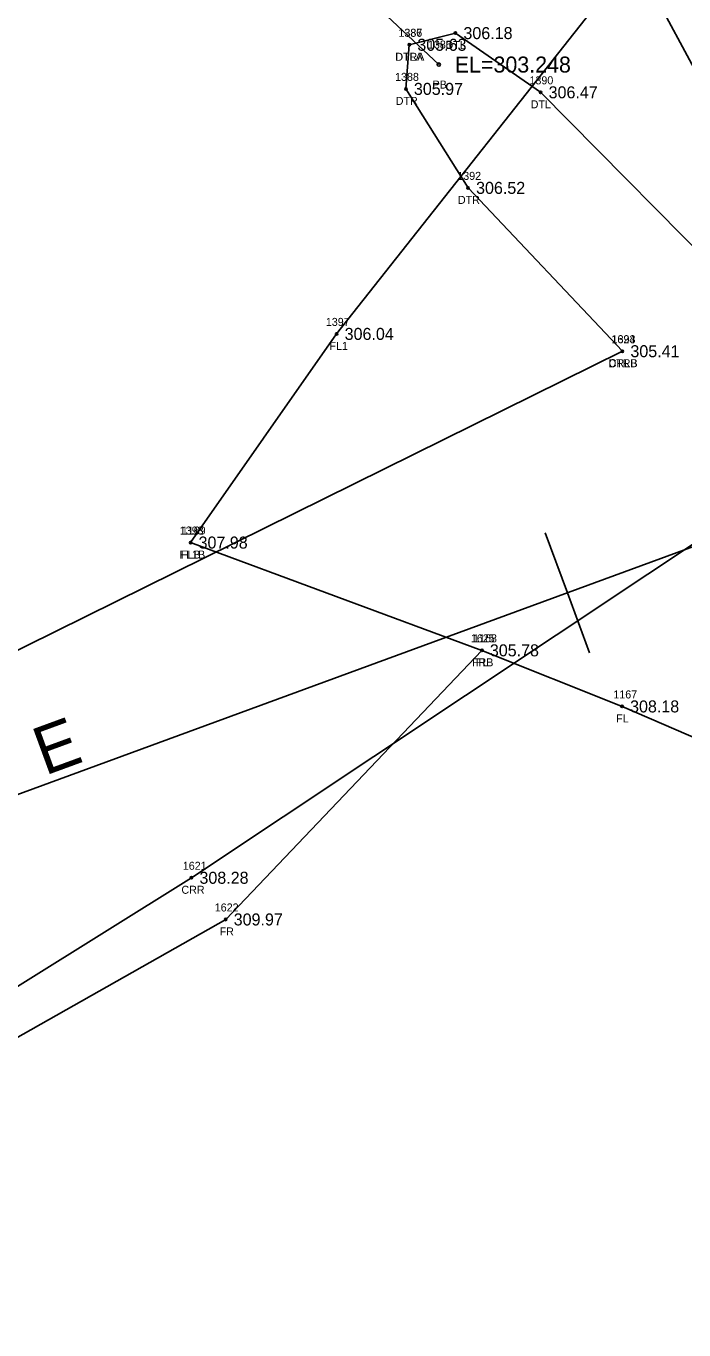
# Model space of a CAD drawing. Extents: x 1865045 to 1867370, y 910391 to 914218.
# Drawn here: x 1866241.8 to 1866324, y 910971.7 to 911134.6 of the extents above; entities that cross this region are included whole.
import ezdxf

# ---------------------------------------------------------------- set-up
doc = ezdxf.new("R2010")
doc.units = 0
for name, color, linetype in [('RD_EX_DR_Pipe', 7, 'Continuous'), ('RD_EX_DR_Pipe_txCode', 7, 'Continuous'), ('RD_EX_Fence_Other', 7, 'Continuous'), ('RD_EX_Fence_Other_txCode', 7, 'Continuous'), ('RD_EX_H2O', 7, 'Continuous'), ('RD_EX_H2O_txCode', 7, 'Continuous'), ('RD_EX_TX_Fence_Other_ELEV', 7, 'Continuous'), ('RD_EX_TX_H2O_ELEV', 7, 'Continuous'), ('RD_HC_Cl', 7, 'Continuous'), ('RD_HC_Data', 7, 'Continuous'), ('RD_HC_Data_Tic', 7, 'Continuous'), ('RD_SMD_Locator', 7, 'Continuous'), ('RD_TX_Pipe_ElevEX', 7, 'Continuous')]:
    doc.layers.add(name, color=color, linetype=linetype)

msp = doc.modelspace()

# ---------------------------------------------------------------- linework, layer by layer
at = {"layer": 'RD_EX_DR_Pipe'}
msp.add_line((1866280.05, 911142.32), (1866293.34, 911129.82), dxfattribs=at)
at = {"layer": 'RD_EX_Fence_Other'}
for points in [[(1866328.11, 911123.98), (1866317.73, 911143.27), (1866292.21, 911196.64), (1866254.72, 911273.66), (1866198.8, 911388.88), (1866160.41, 911467.37), (1866132.32, 911522.75), (1866123.76, 911516.89), (1866120.96, 911520.71)], [(1866317.73, 911143.27), (1866280.58, 911096.16), (1866262.33, 911070.09)], [(1866495.48, 910749.21), (1866508.82, 910756.58), (1866493.03, 910785.29), (1866469.81, 910829.93), (1866443.69, 910882.22), (1866422.34, 910922.89), (1866379.46, 911022.29), (1866316.24, 911049.61), (1866298.72, 911056.62), (1866262.33, 911070.09)], [(1865878.66, 910821.99), (1865958.17, 910874.52), (1866026.09, 910916.1), (1866080.13, 910930.26), (1866132.1, 910957.01), (1866200.24, 910985.36), (1866266.72, 911022.99), (1866298.72, 911056.62)]]:
    msp.add_lwpolyline(points, dxfattribs=at)
at = {"layer": 'RD_EX_H2O'}
for points in [[(1866289.66, 911132.29), (1866295.42, 911133.75), (1866306.06, 911126.35), (1866331.08, 911101.06)], [(1866289.66, 911132.29), (1866289.23, 911126.78), (1866297, 911114.41), (1866316.28, 911094)], [(1865881.51, 910820.06), (1865958.27, 910871.4), (1866021.41, 910928.56), (1866077.02, 910947.47), (1866128.62, 910963.47), (1866198.85, 910988.48), (1866262.44, 911028.2), (1866342.24, 911081.3), (1866369.75, 911075.31), (1866430.98, 911110.24)], [(1865861.04, 910849.84), (1865929.7, 910901.29), (1866000.34, 910964.46), (1866054.46, 911008.9), (1866114.23, 911001.05), (1866184.96, 911030.79), (1866234.29, 911053.46), (1866316.28, 911094)]]:
    msp.add_lwpolyline(points, dxfattribs=at)
at = {"layer": 'RD_HC_Cl'}
msp.add_line((1866069.86, 910975.96), (1866379.46, 911089.5), dxfattribs=at)
at = {"layer": 'RD_HC_Data_Tic'}
for q in [(1866306.65, 911071.31), (1866312.15, 911056.29)]:
    msp.add_line((1866309.4, 911063.8), q, dxfattribs=at)
at = {"layer": 'RD_SMD_Locator'}
for centre, radius in [((1866289.66, 911132.29), 0.15), ((1866289.66, 911132.29), 0.15), ((1866295.42, 911133.75), 0.15), ((1866293.34, 911129.82), 0.2), ((1866289.23, 911126.78), 0.15), ((1866306.06, 911126.35), 0.15), ((1866297, 911114.41), 0.15), ((1866280.58, 911096.16), 0.15), ((1866316.28, 911094), 0.15), ((1866316.28, 911094), 0.15), ((1866262.33, 911070.09), 0.15), ((1866262.33, 911070.09), 0.15), ((1866298.72, 911056.62), 0.15), ((1866298.72, 911056.62), 0.15), ((1866316.24, 911049.61), 0.15), ((1866262.44, 911028.2), 0.15), ((1866266.72, 911022.99), 0.15)]:
    msp.add_circle(centre, radius, dxfattribs=at)

# ---------------------------------------------------------------- texts
at = {"layer": 'RD_EX_DR_Pipe_txCode'}
for s, p in [('1385', (1866291.99, 911131.82)), ('PB', (1866292.56, 911126.82))]:
    msp.add_text(s, height=1, dxfattribs=at).set_placement(p)
at = {"layer": 'RD_EX_Fence_Other_txCode'}
for s, p in [('1397', (1866279.23, 911097.16)), ('FL1', (1866279.68, 911094.16)), ('1398', (1866260.98, 911071.09)), ('1169', (1866261.24, 911071.09)), ('FL1B', (1866260.96, 911068.09)), ('FLB', (1866261.12, 911068.09)), ('1625', (1866297.35, 911057.62)), ('1168', (1866297.63, 911057.62)), ('FRB', (1866297.49, 911054.62)), ('FL', (1866297.98, 911054.62)), ('1167', (1866315.15, 911050.61)), ('FL', (1866315.5, 911047.61)), ('1622', (1866265.35, 911023.99)), ('FR', (1866265.96, 911020.99))]:
    msp.add_text(s, height=1, dxfattribs=at).set_placement(p)
at = {"layer": 'RD_EX_H2O_txCode'}
for s, p in [('1386', (1866288.29, 911133.29)), ('1387', (1866288.31, 911133.29)), ('DTL', (1866294.18, 911131.75)), ('DTRA', (1866287.9, 911130.29)), ('DTLA', (1866287.92, 911130.29)), ('1388', (1866287.88, 911127.78)), ('1390', (1866304.67, 911127.35)), ('DTR', (1866287.96, 911124.78)), ('DTL', (1866304.82, 911124.35)), ('1392', (1866295.65, 911115.41)), ('DTR', (1866295.73, 911112.41)), ('1624', (1866314.91, 911095)), ('1393', (1866314.94, 911095)), ('CRLB', (1866314.58, 911092)), ('DTRB', (1866314.54, 911092)), ('1621', (1866261.36, 911029.2)), ('CRR', (1866261.19, 911026.2))]:
    msp.add_text(s, height=1, dxfattribs=at).set_placement(p)
at = {"layer": 'RD_EX_TX_Fence_Other_ELEV'}
for s, p in [('306.04', (1866281.58, 911095.41)), ('307.98', (1866263.33, 911069.34)), ('307.98', (1866263.33, 911069.34)), ('305.78', (1866299.72, 911055.87)), ('305.78', (1866299.72, 911055.87)), ('308.18', (1866317.24, 911048.86)), ('309.97', (1866267.72, 911022.24))]:
    msp.add_text(s, height=1.5, dxfattribs=at).set_placement(p)
at = {"layer": 'RD_EX_TX_H2O_ELEV'}
for s, p in [('306.18', (1866296.42, 911133)), ('305.63', (1866290.66, 911131.54)), ('305.63', (1866290.66, 911131.54)), ('305.97', (1866290.23, 911126.03)), ('306.47', (1866307.06, 911125.6)), ('306.52', (1866298, 911113.66)), ('305.41', (1866317.28, 911093.25)), ('305.41', (1866317.28, 911093.25)), ('308.28', (1866263.44, 911027.45))]:
    msp.add_text(s, height=1.5, dxfattribs=at).set_placement(p)
at = {"layer": 'RD_HC_Data'}
msp.add_text('N 69%%d 51\' 41" E', height=6, rotation=20.1386, dxfattribs=at).set_placement((1866198.05, 911024.04))
at = {"layer": 'RD_TX_Pipe_ElevEX'}
msp.add_text('EL=303.248', height=2, dxfattribs=at).set_placement((1866295.34, 911128.82))

doc.saveas('drawing.dxf')
